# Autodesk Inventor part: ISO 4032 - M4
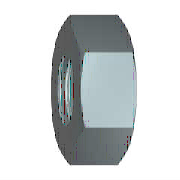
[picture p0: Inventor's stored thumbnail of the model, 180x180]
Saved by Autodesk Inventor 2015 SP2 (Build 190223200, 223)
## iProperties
IsCustomPart: 0
Created: 2012-02
Part Number: ISO 4032 - M4
Material: Edelstahl, 440C
Description: Sechskantmuttern, Typ 1 - Produktklasse A und B
Document SubType Name: Modeling
Standard: ISO 4032
Designer: rYan
Standard Revision: Third edition 1999-08-15
Standards Organization: ISO
Language: de-DE
Size Designation: M4
Categories: <MemberInstance><Categories><Category DisplayName="Verbindungselemente" InternalName="e4da775c-781d-43d5-af7c-5136215cf5a6" Mnemonic="FSTN"><Category DisplayNam
Density: 7.75 g/cm^3
Appearance: Halbpoliert
Author: rYan
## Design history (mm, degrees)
sketch "Skizze1"
  geometry: L1 (-4.041, 0)-(-2.021, 3.5); L2 (-2.021, 3.5)-(2.021, 3.5); L3 (2.021, 3.5)-(4.041, 0); L4 (4.041, 0)-(2.021, -3.5); L5 (2.021, -3.5)-(-2.021, -3.5); L6 (-2.021, -3.5)-(-4.041, 0); 2 further points
  constraints: 12 end point, 1 coincident, 1 horizontal, 11 other
  dimensions: "d0" = 8.0829 distance of L3.end L1.start (= 1.1547 x SW)
extrude "Körper" new body sketch "Skizze1" distance "d1" = 3.2 (= KOH); taper "d2" = 0 deg
sketch "Skizze2"
  geometry: L1 (0, 2.021)-(0, 4.041) reference; L2 (0, 4.041)-(3.2, 4.041) reference; L3 (3.2, 2.021)-(3.2, 4.041) reference; L4 (-0.64, 0)-(3.84, 0) reference; L5 (0.63, 4.041)-(0, 2.95); L6 (2.57, 4.041)-(3.2, 2.95)
  constraints: 4 end point, 4 point on line
  dimensions: "d3" = 30 deg angle of L1 L5 (= ANG1); "d4" = 30 deg angle of L3 L6 (= ANG2); "d5" = 5.9 diameter of L5.end L4 (= SW0); "d6" = 5.9 diameter of L6.end L4 (= SW01)
revolve "Fase1" sketch "Skizze2" stored, may be unused: angle "d7" = 90 deg
sketch "Skizze3"
  geometry: 4 further points
  constraints: 1 coincident, 1 other
hole "Gewinde" sketch "Skizze3" at (0, 0) diameter "d25" = 3.242; stored, may be unused: countersink angle "d29" = 82 deg, drill point angle "d31" = 118 deg; dims "d26" = 6, "d27" = 4, "d28" = 2, "d30" = 8
workaxis "Work Axis1"
workplane "Work Plane1"
body "Solid1"
chamfer "Fase2" distance "d8" = 0.37889 (= -0.5 x GD1 + 0.5 x NND); stored, may be unused: angle "d9" = 30 deg, second distance "d40" = 0.37889 (= -0.5 x GD1 + 0.5 x NND)
chamfer "Fase3" distance "d10" = 0.37889 (= -0.5 x GD1 + 0.5 x NND); stored, may be unused: angle "d11" = 30 deg, second distance "d41" = 0.37889 (= -0.5 x GD1 + 0.5 x NND)
other parameters: "ANG1" = 30 deg [user parameter; used in 1 equation term], "ANG2" = 30 deg [user parameter; used in 1 equation term], "NND" = 4 [user parameter; used in 4 equation terms], "KOH" = 3.2 [user parameter; used in 1 equation term], "SW" = 7 [user parameter; used in 2 equation terms], "SW0" = 5.9 [user parameter; used in 2 equation terms], "SW01" = 5.9 (= SW0) [user parameter; used in 1 equation term], "GD1" = 3.24223 (computed from THREADDIA, PTC, TOA) [user parameter; used in 4 equation terms], "d13" = 0, "d14" = 0, "d39" = 0, "d42" = 0, "GUL" = 0.37889 (= 0.541266 x PTC) [user parameter], "TPU" = 14.28571 (computed from PTC) [user parameter], "THREADDIA" = 4 [user parameter; used in 1 equation term], "TOA" = 30 deg [user parameter; used in 1 equation term], "PTC" = 0.7 [user parameter; used in 4 equation terms], "E0" = 8.085 (= 1.155 x SW) [user parameter], "GAL" = 0.37889 (= 0.541266 x PTC) [user parameter]
